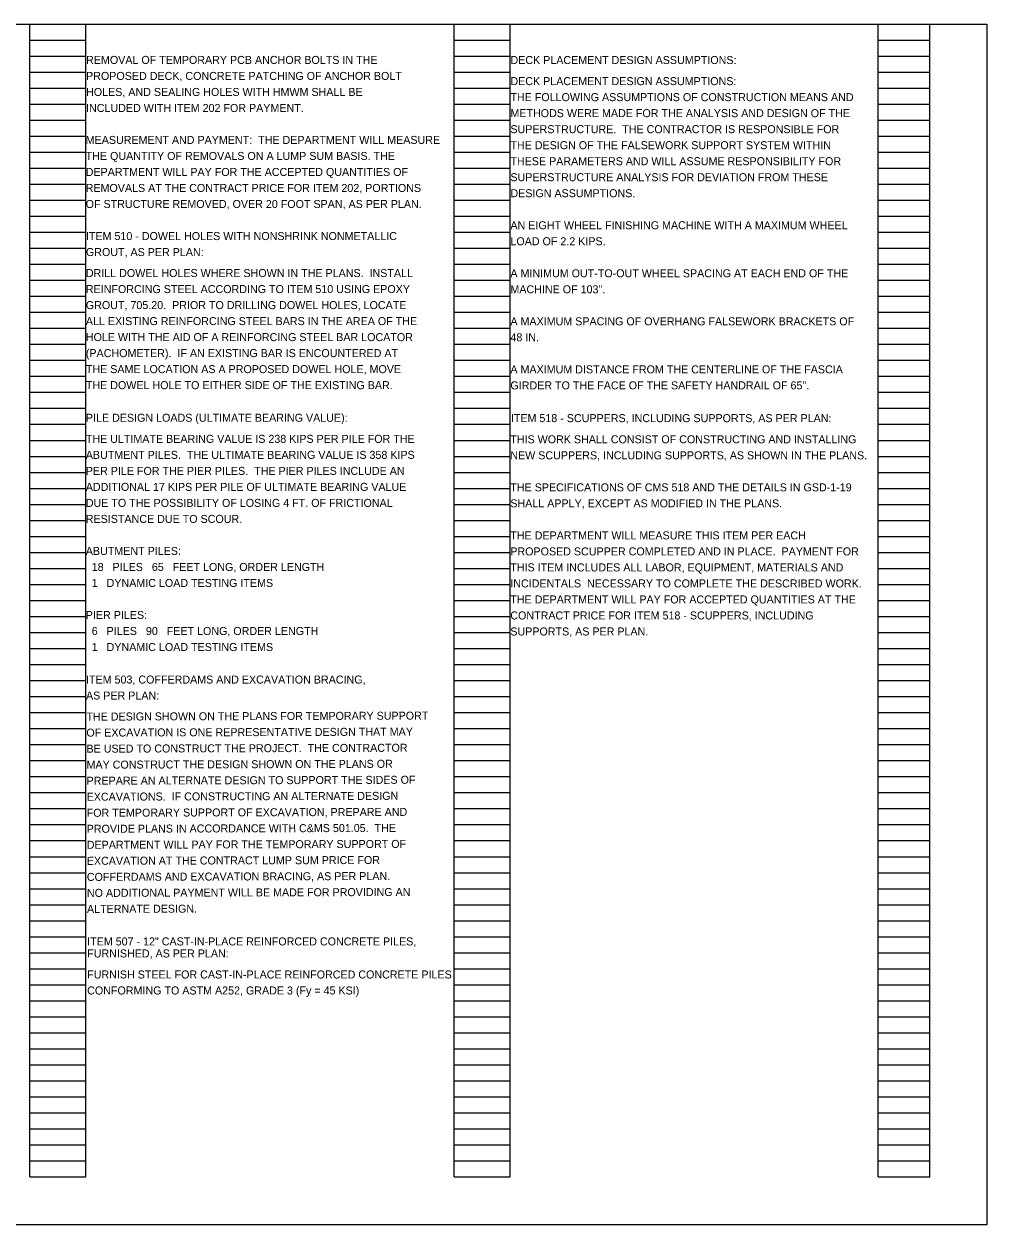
# Model space of a CAD drawing. Extents: x 8.9 to 72, y -18.6 to 3.4.
# Drawn here: x 25.52 to 42.36, y -18.43 to 2.57 of the extents above; entities that cross this region are included whole.
import ezdxf

# ---------------------------------------------------------------- set-up
doc = ezdxf.new("R2010")
doc.units = 0
for name, color, linetype in [('BR_P_Gen_Text', 7, 'Continuous'), ('SC_Scratch1', 7, 'Continuous'), ('SH_Data', 7, 'Continuous')]:
    doc.layers.add(name, color=color, linetype=linetype)

msp = doc.modelspace()

# ---------------------------------------------------------------- linework, layer by layer
at = {"layer": 'SC_Scratch1'}
msp.add_lwpolyline([(10.858, 2.575), (42.358, 2.575), (42.358, -18.425), (10.858, -18.425)], close=True, dxfattribs=at)
at = {"layer": 'SH_Data'}
for p, q in [((25.618, -17.585), (25.618, 2.575)), ((25.618, 2.575), (26.598, 2.575)), ((26.598, -17.585), (26.598, 2.575)), ((33.038, -17.585), (33.038, 2.575)), ((33.038, 2.575), (34.018, 2.575)), ((34.018, -17.585), (34.018, 2.575)), ((40.458, -17.585), (40.458, 2.575)), ((40.458, 2.575), (41.358, 2.575)), ((41.358, -17.585), (41.358, 2.575)), ((25.618, 2.295), (26.598, 2.295)), ((33.038, 2.295), (34.018, 2.295)), ((40.458, 2.295), (41.358, 2.295)), ((25.618, 2.015), (26.598, 2.015)), ((33.038, 2.015), (34.018, 2.015)), ((40.458, 2.015), (41.358, 2.015)), ((25.618, 1.735), (26.598, 1.735)), ((33.038, 1.735), (34.018, 1.735)), ((40.458, 1.735), (41.358, 1.735)), ((25.618, 1.455), (26.598, 1.455)), ((33.038, 1.455), (34.018, 1.455)), ((40.458, 1.455), (41.358, 1.455)), ((25.618, 1.175), (26.598, 1.175)), ((33.038, 1.175), (34.018, 1.175)), ((40.458, 1.175), (41.358, 1.175)), ((25.618, 0.895), (26.598, 0.895)), ((33.038, 0.895), (34.018, 0.895)), ((40.458, 0.895), (41.358, 0.895)), ((25.618, 0.615), (26.598, 0.615)), ((33.038, 0.615), (34.018, 0.615)), ((40.458, 0.615), (41.358, 0.615)), ((25.618, 0.335), (26.598, 0.335)), ((33.038, 0.335), (34.018, 0.335)), ((40.458, 0.335), (41.358, 0.335)), ((25.618, 0.055), (26.598, 0.055)), ((33.038, 0.055), (34.018, 0.055)), ((40.458, 0.055), (41.358, 0.055)), ((25.618, -0.225), (26.598, -0.225)), ((33.038, -0.225), (34.018, -0.225)), ((40.458, -0.225), (41.358, -0.225)), ((25.618, -0.505), (26.598, -0.505)), ((33.038, -0.505), (34.018, -0.505)), ((40.458, -0.505), (41.358, -0.505)), ((25.618, -0.785), (26.598, -0.785)), ((33.038, -0.785), (34.018, -0.785)), ((40.458, -0.785), (41.358, -0.785)), ((25.618, -1.065), (26.598, -1.065)), ((33.038, -1.065), (34.018, -1.065)), ((40.458, -1.065), (41.358, -1.065)), ((25.618, -1.345), (26.598, -1.345)), ((33.038, -1.345), (34.018, -1.345)), ((40.458, -1.345), (41.358, -1.345)), ((25.618, -1.625), (26.598, -1.625)), ((33.038, -1.625), (34.018, -1.625)), ((40.458, -1.625), (41.358, -1.625)), ((25.618, -1.905), (26.598, -1.905)), ((33.038, -1.905), (34.018, -1.905)), ((40.458, -1.905), (41.358, -1.905)), ((25.618, -2.185), (26.598, -2.185)), ((33.038, -2.185), (34.018, -2.185)), ((40.458, -2.185), (41.358, -2.185)), ((25.618, -2.465), (26.598, -2.465)), ((33.038, -2.465), (34.018, -2.465)), ((40.458, -2.465), (41.358, -2.465)), ((25.618, -2.745), (26.598, -2.745)), ((33.038, -2.745), (34.018, -2.745)), ((40.458, -2.745), (41.358, -2.745)), ((25.618, -3.025), (26.598, -3.025)), ((33.038, -3.025), (34.018, -3.025)), ((40.458, -3.025), (41.358, -3.025)), ((25.618, -3.305), (26.598, -3.305)), ((33.038, -3.305), (34.018, -3.305)), ((40.458, -3.305), (41.358, -3.305)), ((25.618, -3.585), (26.598, -3.585)), ((33.038, -3.585), (34.018, -3.585)), ((40.458, -3.585), (41.358, -3.585)), ((25.618, -3.865), (26.598, -3.865)), ((33.038, -3.865), (34.018, -3.865)), ((40.458, -3.865), (41.358, -3.865)), ((25.618, -4.145), (26.598, -4.145)), ((33.038, -4.145), (34.018, -4.145)), ((40.458, -4.145), (41.358, -4.145)), ((25.618, -4.425), (26.598, -4.425)), ((33.038, -4.425), (34.018, -4.425)), ((40.458, -4.425), (41.358, -4.425)), ((25.618, -4.705), (26.598, -4.705)), ((33.038, -4.705), (34.018, -4.705)), ((40.458, -4.705), (41.358, -4.705)), ((25.618, -4.985), (26.598, -4.985)), ((33.038, -4.985), (34.018, -4.985)), ((40.458, -4.985), (41.358, -4.985)), ((25.618, -5.265), (26.598, -5.265)), ((33.038, -5.265), (34.018, -5.265)), ((40.458, -5.265), (41.358, -5.265)), ((25.618, -5.545), (26.598, -5.545)), ((33.038, -5.545), (34.018, -5.545)), ((40.458, -5.545), (41.358, -5.545)), ((25.618, -5.825), (26.598, -5.825)), ((33.038, -5.825), (34.018, -5.825)), ((40.458, -5.825), (41.358, -5.825)), ((25.618, -6.105), (26.598, -6.105)), ((33.038, -6.105), (34.018, -6.105)), ((40.458, -6.105), (41.358, -6.105)), ((25.618, -6.385), (26.598, -6.385)), ((33.038, -6.385), (34.018, -6.385)), ((40.458, -6.385), (41.358, -6.385)), ((25.618, -6.665), (26.598, -6.665)), ((33.038, -6.665), (34.018, -6.665)), ((40.458, -6.665), (41.358, -6.665)), ((25.618, -6.945), (26.598, -6.945)), ((33.038, -6.945), (34.018, -6.945)), ((40.458, -6.945), (41.358, -6.945)), ((25.618, -7.225), (26.598, -7.225)), ((33.038, -7.225), (34.018, -7.225)), ((40.458, -7.225), (41.358, -7.225)), ((25.618, -7.505), (26.598, -7.505)), ((33.038, -7.505), (34.018, -7.505)), ((40.458, -7.505), (41.358, -7.505)), ((25.618, -7.785), (26.598, -7.785)), ((33.038, -7.785), (34.018, -7.785)), ((40.458, -7.785), (41.358, -7.785)), ((25.618, -8.065), (26.598, -8.065)), ((33.038, -8.065), (34.018, -8.065)), ((40.458, -8.065), (41.358, -8.065)), ((25.618, -8.345), (26.598, -8.345)), ((33.038, -8.345), (34.018, -8.345)), ((40.458, -8.345), (41.358, -8.345)), ((25.618, -8.625), (26.598, -8.625)), ((33.038, -8.625), (34.018, -8.625)), ((40.458, -8.625), (41.358, -8.625)), ((25.618, -8.905), (26.598, -8.905)), ((33.038, -8.905), (34.018, -8.905)), ((40.458, -8.905), (41.358, -8.905)), ((25.618, -9.185), (26.598, -9.185)), ((33.038, -9.185), (34.018, -9.185)), ((40.458, -9.185), (41.358, -9.185)), ((25.618, -9.465), (26.598, -9.465)), ((33.038, -9.465), (34.018, -9.465)), ((40.458, -9.465), (41.358, -9.465)), ((25.618, -9.745), (26.598, -9.745)), ((33.038, -9.745), (34.018, -9.745)), ((40.458, -9.745), (41.358, -9.745)), ((25.618, -10.025), (26.598, -10.025)), ((33.038, -10.025), (34.018, -10.025)), ((40.458, -10.025), (41.358, -10.025)), ((25.618, -10.305), (26.598, -10.305)), ((33.038, -10.305), (34.018, -10.305)), ((40.458, -10.305), (41.358, -10.305)), ((25.618, -10.585), (26.598, -10.585)), ((33.038, -10.585), (34.018, -10.585)), ((40.458, -10.585), (41.358, -10.585)), ((25.618, -10.865), (26.598, -10.865)), ((33.038, -10.865), (34.018, -10.865)), ((40.458, -10.865), (41.358, -10.865)), ((25.618, -11.145), (26.598, -11.145)), ((33.038, -11.145), (34.018, -11.145)), ((40.458, -11.145), (41.358, -11.145)), ((25.618, -11.425), (26.598, -11.425)), ((33.038, -11.425), (34.018, -11.425)), ((40.458, -11.425), (41.358, -11.425)), ((25.618, -11.705), (26.598, -11.705)), ((33.038, -11.705), (34.018, -11.705)), ((40.458, -11.705), (41.358, -11.705)), ((25.618, -11.985), (26.598, -11.985)), ((33.038, -11.985), (34.018, -11.985)), ((40.458, -11.985), (41.358, -11.985)), ((25.618, -12.265), (26.598, -12.265)), ((33.038, -12.265), (34.018, -12.265)), ((40.458, -12.265), (41.358, -12.265)), ((25.618, -12.545), (26.598, -12.545)), ((33.038, -12.545), (34.018, -12.545)), ((40.458, -12.545), (41.358, -12.545)), ((25.618, -12.825), (26.598, -12.825)), ((33.038, -12.825), (34.018, -12.825)), ((40.458, -12.825), (41.358, -12.825)), ((25.618, -13.105), (26.598, -13.105)), ((33.038, -13.105), (34.018, -13.105)), ((40.458, -13.105), (41.358, -13.105)), ((25.618, -13.385), (26.598, -13.385)), ((33.038, -13.385), (34.018, -13.385)), ((40.458, -13.385), (41.358, -13.385)), ((25.618, -13.665), (26.598, -13.665)), ((33.038, -13.665), (34.018, -13.665)), ((40.458, -13.665), (41.358, -13.665)), ((25.618, -13.945), (26.598, -13.945)), ((33.038, -13.945), (34.018, -13.945)), ((40.458, -13.945), (41.358, -13.945)), ((25.618, -14.225), (26.598, -14.225)), ((33.038, -14.225), (34.018, -14.225)), ((40.458, -14.225), (41.358, -14.225)), ((25.618, -14.505), (26.598, -14.505)), ((33.038, -14.505), (34.018, -14.505)), ((40.458, -14.505), (41.358, -14.505)), ((25.618, -14.785), (26.598, -14.785)), ((33.038, -14.785), (34.018, -14.785)), ((40.458, -14.785), (41.358, -14.785)), ((25.618, -15.065), (26.598, -15.065)), ((33.038, -15.065), (34.018, -15.065)), ((40.458, -15.065), (41.358, -15.065)), ((25.618, -15.345), (26.598, -15.345)), ((33.038, -15.345), (34.018, -15.345)), ((40.458, -15.345), (41.358, -15.345)), ((25.618, -15.625), (26.598, -15.625)), ((33.038, -15.625), (34.018, -15.625)), ((40.458, -15.625), (41.358, -15.625)), ((25.618, -15.905), (26.598, -15.905)), ((33.038, -15.905), (34.018, -15.905)), ((40.458, -15.905), (41.358, -15.905)), ((25.618, -16.185), (26.598, -16.185)), ((33.038, -16.185), (34.018, -16.185)), ((40.458, -16.185), (41.358, -16.185)), ((25.618, -16.465), (26.598, -16.465)), ((33.038, -16.465), (34.018, -16.465)), ((40.458, -16.465), (41.358, -16.465)), ((25.618, -16.745), (26.598, -16.745)), ((33.038, -16.745), (34.018, -16.745)), ((40.458, -16.745), (41.358, -16.745)), ((25.618, -17.025), (26.598, -17.025)), ((33.038, -17.025), (34.018, -17.025)), ((40.458, -17.025), (41.358, -17.025)), ((25.618, -17.305), (26.598, -17.305)), ((33.038, -17.305), (34.018, -17.305)), ((40.458, -17.305), (41.358, -17.305)), ((25.618, -17.585), (26.598, -17.585)), ((33.038, -17.585), (34.018, -17.585)), ((40.458, -17.585), (41.358, -17.585))]:
    msp.add_line(p, q, dxfattribs=at)

# ---------------------------------------------------------------- texts
at = {"layer": 'BR_P_Gen_Text'}
for s, p in [('REMOVAL OF TEMPORARY PCB ANCHOR BOLTS IN THE ', (26.601, 1.877)), ('DECK PLACEMENT DESIGN ASSUMPTIONS:', (34.024, 1.875)), ('PROPOSED DECK, CONCRETE PATCHING OF ANCHOR BOLT ', (26.601, 1.597)), ('DECK PLACEMENT DESIGN ASSUMPTIONS:', (34.023, 1.506)), ('HOLES, AND SEALING HOLES WITH HMWM SHALL BE ', (26.601, 1.317)), ('THE FOLLOWING ASSUMPTIONS OF CONSTRUCTION MEANS AND', (34.023, 1.226)), ('INCLUDED WITH ITEM 202 FOR PAYMENT.', (26.601, 1.037)), ('METHODS WERE MADE FOR THE ANALYSIS AND DESIGN OF THE', (34.023, 0.946)), ('SUPERSTRUCTURE.  THE CONTRACTOR IS RESPONSIBLE FOR', (34.023, 0.666)), ('MEASUREMENT AND PAYMENT:  THE DEPARTMENT WILL MEASURE', (26.594, 0.478)), ('THE DESIGN OF THE FALSEWORK SUPPORT SYSTEM WITHIN', (34.023, 0.386)), ('THE QUANTITY OF REMOVALS ON A LUMP SUM BASIS. THE', (26.594, 0.198)), ('THESE PARAMETERS AND WILL ASSUME RESPONSIBILITY FOR', (34.023, 0.106)), ('DEPARTMENT WILL PAY FOR THE ACCEPTED QUANTITIES OF', (26.594, -0.082)), ('SUPERSTRUCTURE ANALYSIS FOR DEVIATION FROM THESE', (34.023, -0.174)), ('REMOVALS AT THE CONTRACT PRICE FOR ITEM 202, PORTIONS', (26.594, -0.362)), ('DESIGN ASSUMPTIONS.', (34.023, -0.454)), ('OF STRUCTURE REMOVED, OVER 20 FOOT SPAN, AS PER PLAN.', (26.594, -0.642)), ('AN EIGHT WHEEL FINISHING MACHINE WITH A MAXIMUM WHEEL', (34.023, -1.014)), ('ITEM 510 - DOWEL HOLES WITH NONSHRINK NONMETALLIC', (26.598, -1.203)), ('LOAD OF 2.2 KIPS.', (34.023, -1.294)), ('GROUT, AS PER PLAN:', (26.598, -1.483)), ('DRILL DOWEL HOLES WHERE SHOWN IN THE PLANS.  INSTALL', (26.597, -1.85)), ('A MINIMUM OUT-TO-OUT WHEEL SPACING AT EACH END OF THE', (34.023, -1.854)), ('REINFORCING STEEL ACCORDING TO ITEM 510 USING EPOXY', (26.597, -2.13)), ('MACHINE OF 103".', (34.023, -2.134)), ('GROUT, 705.20.  PRIOR TO DRILLING DOWEL HOLES, LOCATE', (26.597, -2.41)), ('ALL EXISTING REINFORCING STEEL BARS IN THE AREA OF THE', (26.597, -2.69)), ('A MAXIMUM SPACING OF OVERHANG FALSEWORK BRACKETS OF', (34.023, -2.694)), ('HOLE WITH THE AID OF A REINFORCING STEEL BAR LOCATOR', (26.597, -2.97)), ('48 IN.', (34.023, -2.974)), ('(PACHOMETER).  IF AN EXISTING BAR IS ENCOUNTERED AT ', (26.597, -3.25)), ('THE SAME LOCATION AS A PROPOSED DOWEL HOLE, MOVE', (26.597, -3.53)), ('A MAXIMUM DISTANCE FROM THE CENTERLINE OF THE FASCIA', (34.023, -3.534)), ('THE DOWEL HOLE TO EITHER SIDE OF THE EXISTING BAR. ', (26.597, -3.81)), ('GIRDER TO THE FACE OF THE SAFETY HANDRAIL OF 65".', (34.023, -3.814)), ('PILE DESIGN LOADS (ULTIMATE BEARING VALUE):', (26.598, -4.38)), ('ITEM 518 - SCUPPERS, INCLUDING SUPPORTS, AS PER PLAN:', (34.031, -4.387)), ('THE ULTIMATE BEARING VALUE IS 238 KIPS PER PILE FOR THE ', (26.596, -4.749)), ('THIS WORK SHALL CONSIST OF CONSTRUCTING AND INSTALLING', (34.021, -4.757)), ('ABUTMENT PILES.  THE ULTIMATE BEARING VALUE IS 358 KIPS ', (26.596, -5.029)), ('NEW SCUPPERS, INCLUDING SUPPORTS, AS SHOWN IN THE PLANS.', (34.021, -5.037)), ('PER PILE FOR THE PIER PILES.  THE PIER PILES INCLUDE AN ', (26.596, -5.309)), ('ADDITIONAL 17 KIPS PER PILE OF ULTIMATE BEARING VALUE', (26.596, -5.589)), ('THE SPECIFICATIONS OF CMS 518 AND THE DETAILS IN GSD-1-19', (34.021, -5.597)), ('DUE TO THE POSSIBILITY OF LOSING 4 FT. OF FRICTIONAL ', (26.596, -5.869)), ('SHALL APPLY, EXCEPT AS MODIFIED IN THE PLANS.', (34.021, -5.877)), ('RESISTANCE DUE TO SCOUR.', (26.596, -6.149)), ('THE DEPARTMENT WILL MEASURE THIS ITEM PER EACH', (34.021, -6.437)), ('ABUTMENT PILES:', (26.596, -6.709)), ('PROPOSED SCUPPER COMPLETED AND IN PLACE.  PAYMENT FOR', (34.021, -6.717)), ('  18   PILES   65   FEET LONG, ORDER LENGTH', (26.596, -6.989)), ('THIS ITEM INCLUDES ALL LABOR, EQUIPMENT, MATERIALS AND', (34.021, -6.997)), ('  1   DYNAMIC LOAD TESTING ITEMS', (26.596, -7.269)), ('INCIDENTALS  NECESSARY TO COMPLETE THE DESCRIBED WORK.', (34.021, -7.277)), ('THE DEPARTMENT WILL PAY FOR ACCEPTED QUANTITIES AT THE', (34.021, -7.557)), ('PIER PILES:', (26.596, -7.829)), ('CONTRACT PRICE FOR ITEM 518 - SCUPPERS, INCLUDING ', (34.021, -7.837)), ('  6   PILES   90   FEET LONG, ORDER LENGTH', (26.596, -8.109)), ('SUPPORTS, AS PER PLAN. ', (34.021, -8.117)), ('  1   DYNAMIC LOAD TESTING ITEMS', (26.596, -8.389)), ('ITEM 503, COFFERDAMS AND EXCAVATION BRACING,', (26.6, -8.958)), ('AS PER PLAN:', (26.6, -9.238)), ('ITEM 507 - 12" CAST-IN-PLACE REINFORCED CONCRETE PILES,', (26.62, -13.537)), ('FURNISHED, AS PER PLAN:', (26.62, -13.747)), ('FURNISH STEEL FOR CAST-IN-PLACE REINFORCED CONCRETE PILES ', (26.62, -14.115)), ('CONFORMING TO ASTM A252, GRADE 3 (Fy = 45 KSI)', (26.62, -14.395))]:
    msp.add_text(s, height=0.14, dxfattribs=at).set_placement(p)
for s, p in [('THE DESIGN SHOWN ON THE PLANS FOR TEMPORARY SUPPORT', (26.607, -9.606)), ('OF EXCAVATION IS ONE REPRESENTATIVE DESIGN THAT MAY ', (26.607, -9.886)), ('BE USED TO CONSTRUCT THE PROJECT.  THE CONTRACTOR', (26.608, -10.167)), ('MAY CONSTRUCT THE DESIGN SHOWN ON THE PLANS OR', (26.609, -10.447)), ('PREPARE AN ALTERNATE DESIGN TO SUPPORT THE SIDES OF', (26.61, -10.727)), ('EXCAVATIONS.  IF CONSTRUCTING AN ALTERNATE DESIGN', (26.611, -11.007)), ('FOR TEMPORARY SUPPORT OF EXCAVATION, PREPARE AND', (26.612, -11.288)), ('PROVIDE PLANS IN ACCORDANCE WITH C&MS 501.05.  THE ', (26.612, -11.568)), ('DEPARTMENT WILL PAY FOR THE TEMPORARY SUPPORT OF', (26.613, -11.848)), ('EXCAVATION AT THE CONTRACT LUMP SUM PRICE FOR', (26.614, -12.128)), ('COFFERDAMS AND EXCAVATION BRACING, AS PER PLAN.   ', (26.615, -12.409)), ('NO ADDITIONAL PAYMENT WILL BE MADE FOR PROVIDING AN ', (26.616, -12.689)), ('ALTERNATE DESIGN.', (26.617, -12.969))]:
    msp.add_text(s, height=0.14, rotation=0.1709, dxfattribs=at).set_placement(p)

doc.saveas('drawing.dxf')
